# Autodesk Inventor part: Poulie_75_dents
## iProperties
Created: 2011-01
Part Number: Poulie_75_dents
Document SubType Name: Modeling
Designer: eric
Density: 1 g/cm^3
Mass: 15.0159 g
Surface Area: 60.9152 cm^2
Volume: 15.0159 cm^3
Author: eric
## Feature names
1. Base1
